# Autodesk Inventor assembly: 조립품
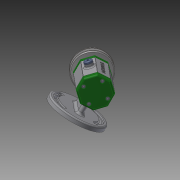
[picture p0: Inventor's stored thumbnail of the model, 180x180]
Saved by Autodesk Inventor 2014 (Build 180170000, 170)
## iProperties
Created: 2017-06
Part Number: 조립품
Document SubType Name: Assembly
Designer: Administrator
Author: Administrator
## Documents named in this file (14)
- C:\Users\Administrator\Desktop\470607v1022\조립품.iam
- C:\Users\Administrator\Desktop\470607v1022\1 본체.ipt
- C:\Users\Administrator\Desktop\470607v1022\V벨트풀리.ipt
- C:\Users\Administrator\Desktop\470607v1022\고무캡.ipt
- C:\Users\Administrator\Desktop\470607v1022\너트 M 8.ipt
- C:\Users\Administrator\Desktop\470607v1022\뒤커버.ipt
- C:\Users\Administrator\Desktop\470607v1022\베어링 15 x 32 x 9.ipt
- C:\Users\Administrator\Desktop\470607v1022\볼트 M4 x 12.ipt
- C:\Users\Administrator\Desktop\470607v1022\스프링와셔 8.ipt
- C:\Users\Administrator\Desktop\470607v1022\앞커버.ipt
- C:\Users\Administrator\Desktop\470607v1022\오일 실 15 25 7.ipt
- C:\Users\Administrator\Desktop\470607v1022\와셔 8x17.ipt
- C:\Users\Administrator\Desktop\470607v1022\축.ipt
- C:\Users\Administrator\Desktop\470607v1022\키 3 x 3 x 12.ipt
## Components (3 placed, 3 different names)
1. 1 본체:1
2. V벨트풀리:1 — 각도:2
3. 고무캡:1
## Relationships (1: Angle 1)
- 각도:2 [Angle]: V벨트풀리:1
